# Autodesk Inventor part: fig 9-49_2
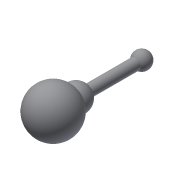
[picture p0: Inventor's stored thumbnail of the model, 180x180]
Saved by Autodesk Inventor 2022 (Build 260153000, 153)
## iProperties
Created: 2013-03
Part Number: fig 9-49_2
Material: Generic
Document SubType Name: Modeling
Designer: CADCIM
Density: 1 g/cm^3
Appearance: Default
Author: CADCIM
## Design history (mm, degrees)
sketch "Sketch1"
  geometry: L1 (0, 5)-(0, -5); A1 r 5 centre (0, 0) between (0, -5) and (0, 5); 1 further point
  constraints: 2 end point, 2 point on circle, 1 centre point, 1 coincident, 1 vertical
  dimensions: "d0" = 10 diameter of A1
revolve "Revolution1" sketch "Sketch1" stored, may be unused: angle "d2" = 90 deg
sketch "Sketch2"
  geometry: L1 (0, 20.921)-(0, 2.139); L2 (1.175, 7.426)-(1.175, 17.742); A1 r 1.807 centre (0, 19.115) between (1.175, 17.742) and (0, 20.921); A2 r 2.774 centre (0, 4.913) between (0, 2.139) and (1.175, 7.426); 1 further point
  constraints: 4 end point, 4 point on circle, 2 centre point, 1 parallel, 1 vertical
revolve "Revolution2" sketch "Sketch2" stored, may be unused: angle "d3" = 90 deg
body "Solid1"
